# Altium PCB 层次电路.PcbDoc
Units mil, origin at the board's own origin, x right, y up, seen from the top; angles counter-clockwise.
Board outline 3000 x 3000 mil, 4 copper layers (Top Layer, VCC, GND, Bottom Layer), stack 30.634 mil thick; 34 components, 49 nets, 170 pads, 0 vias.
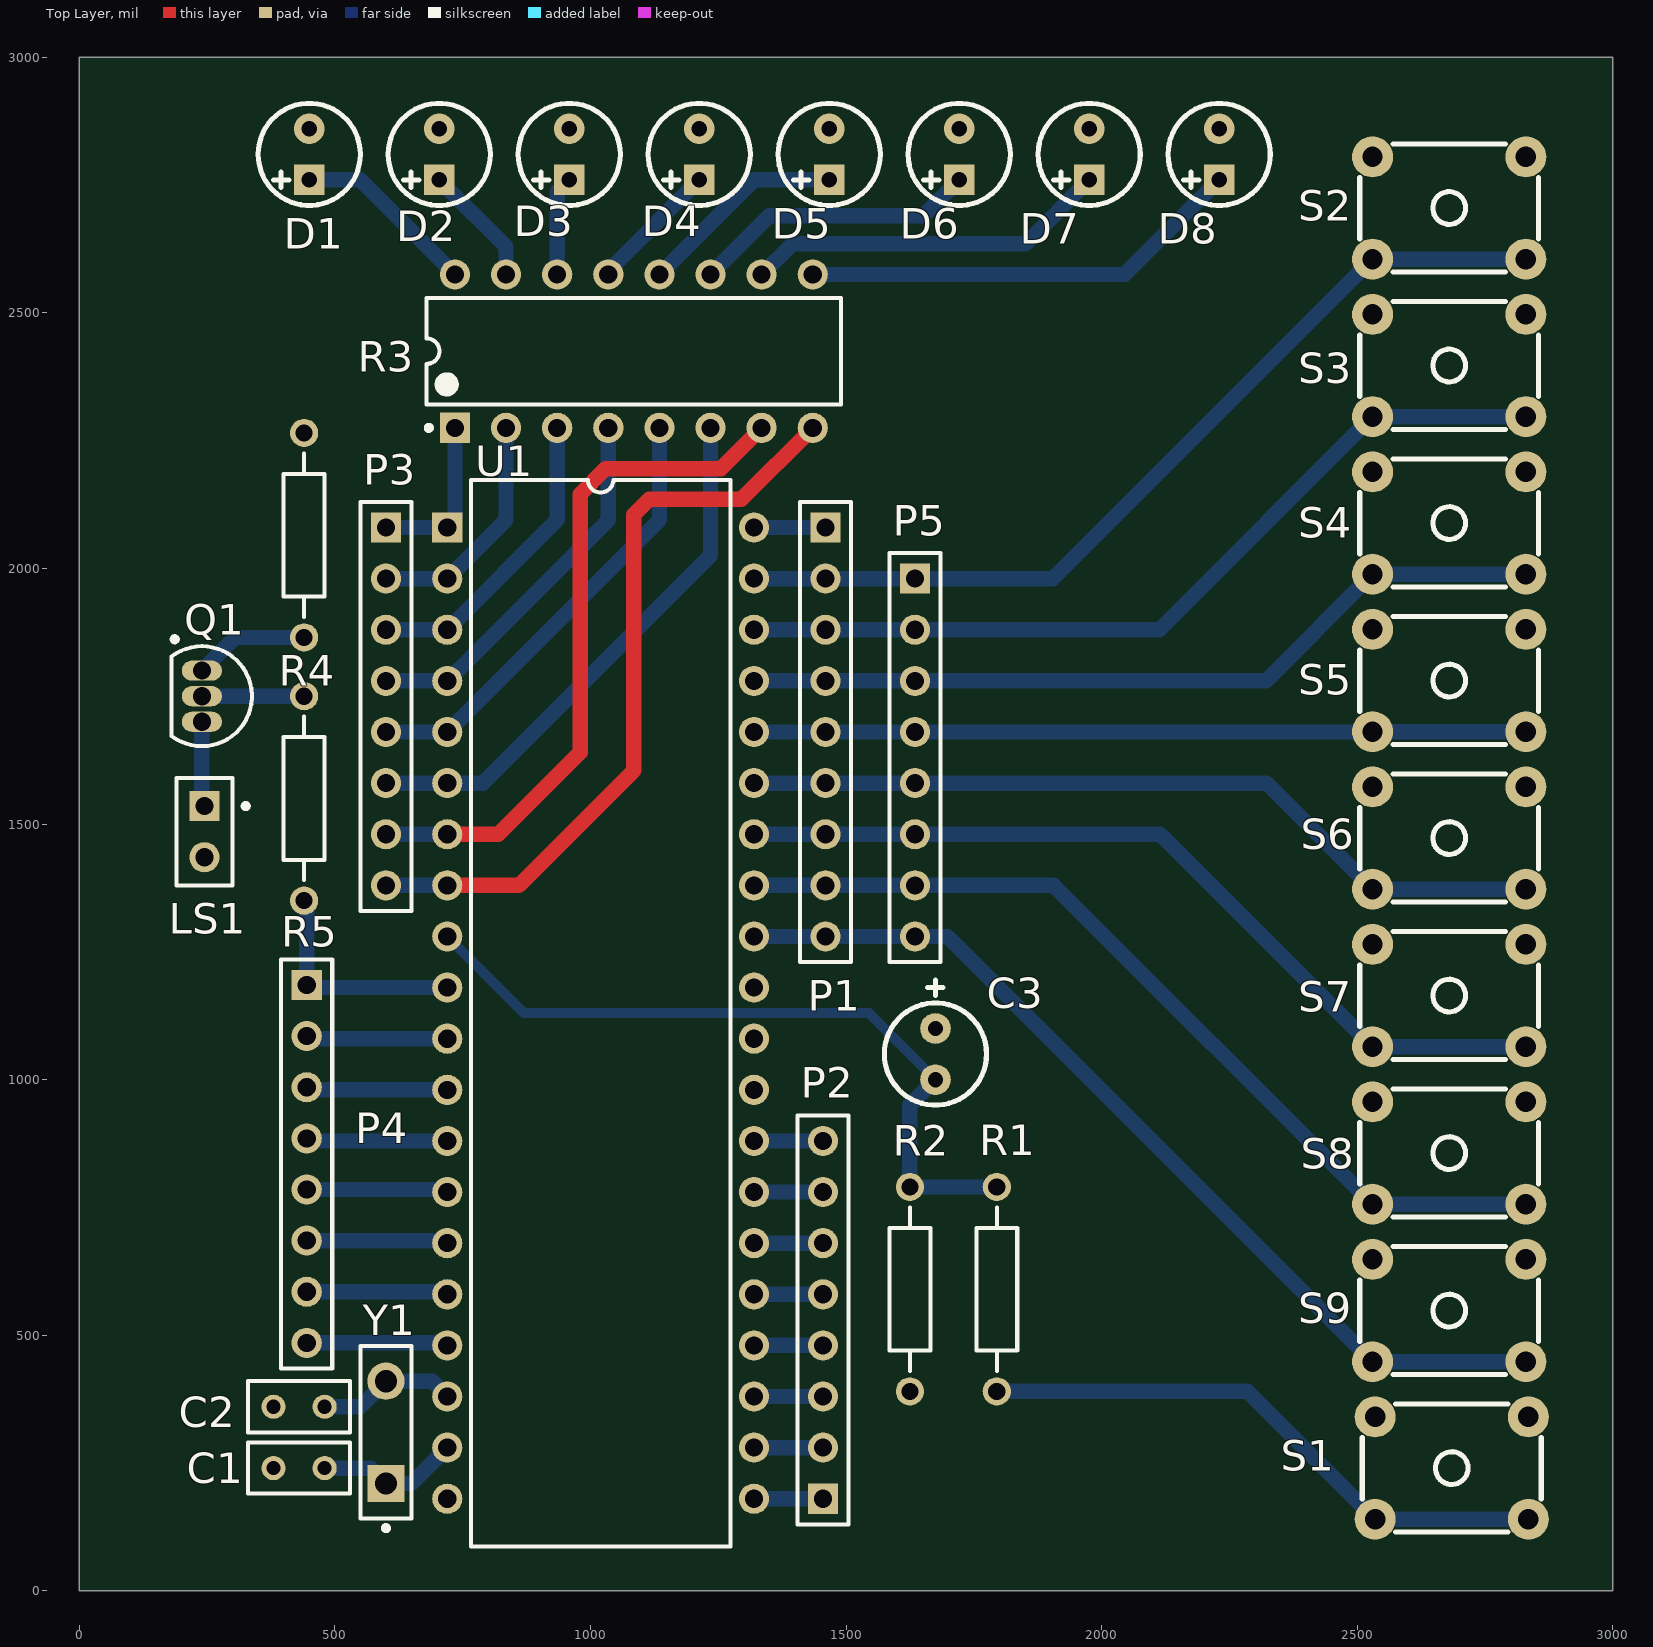
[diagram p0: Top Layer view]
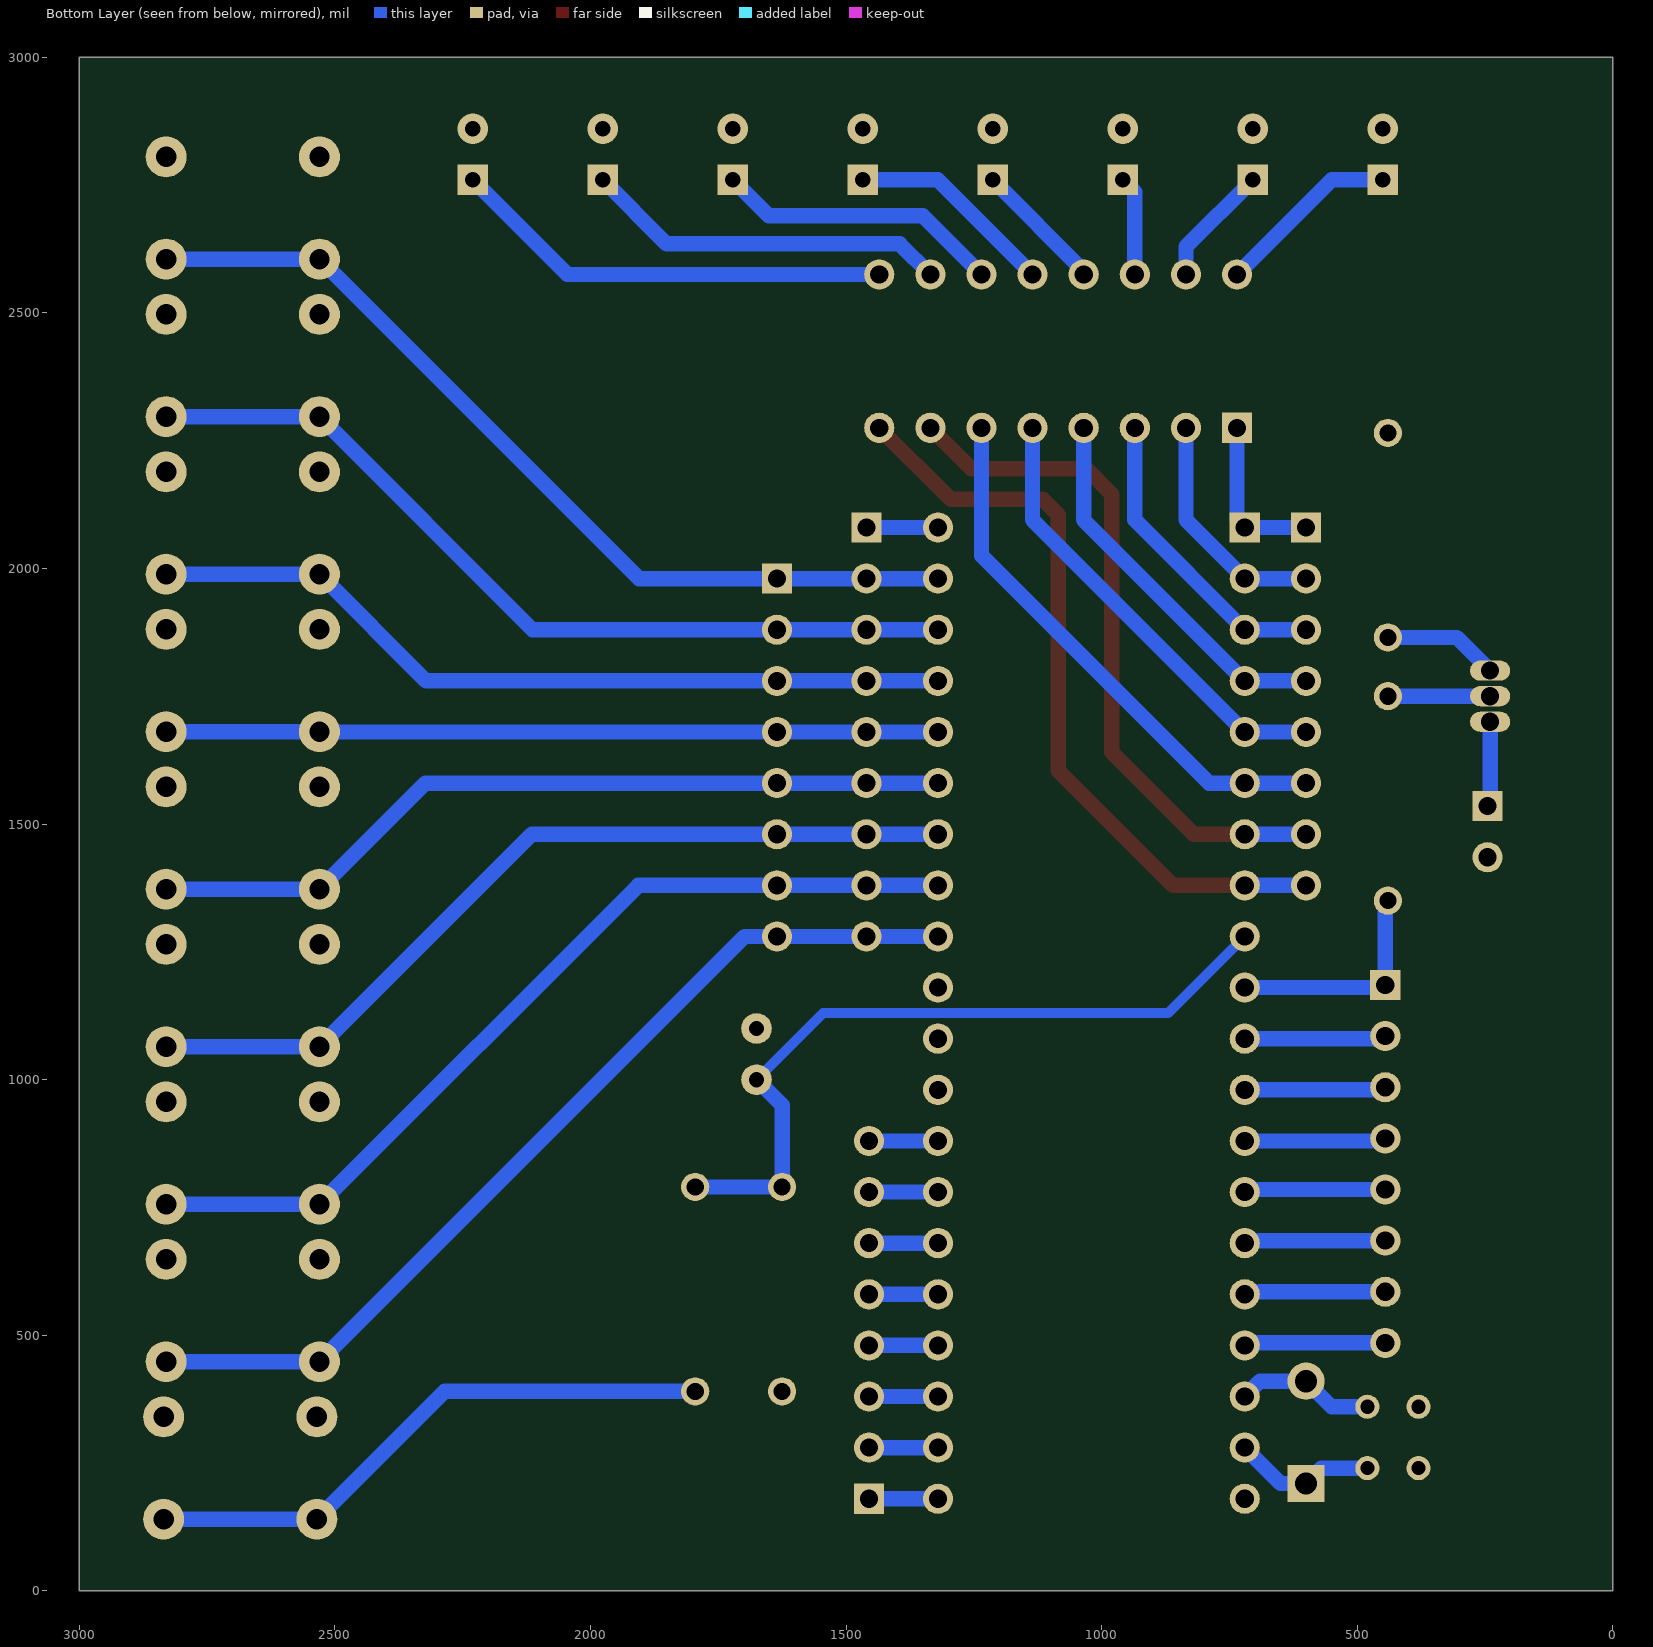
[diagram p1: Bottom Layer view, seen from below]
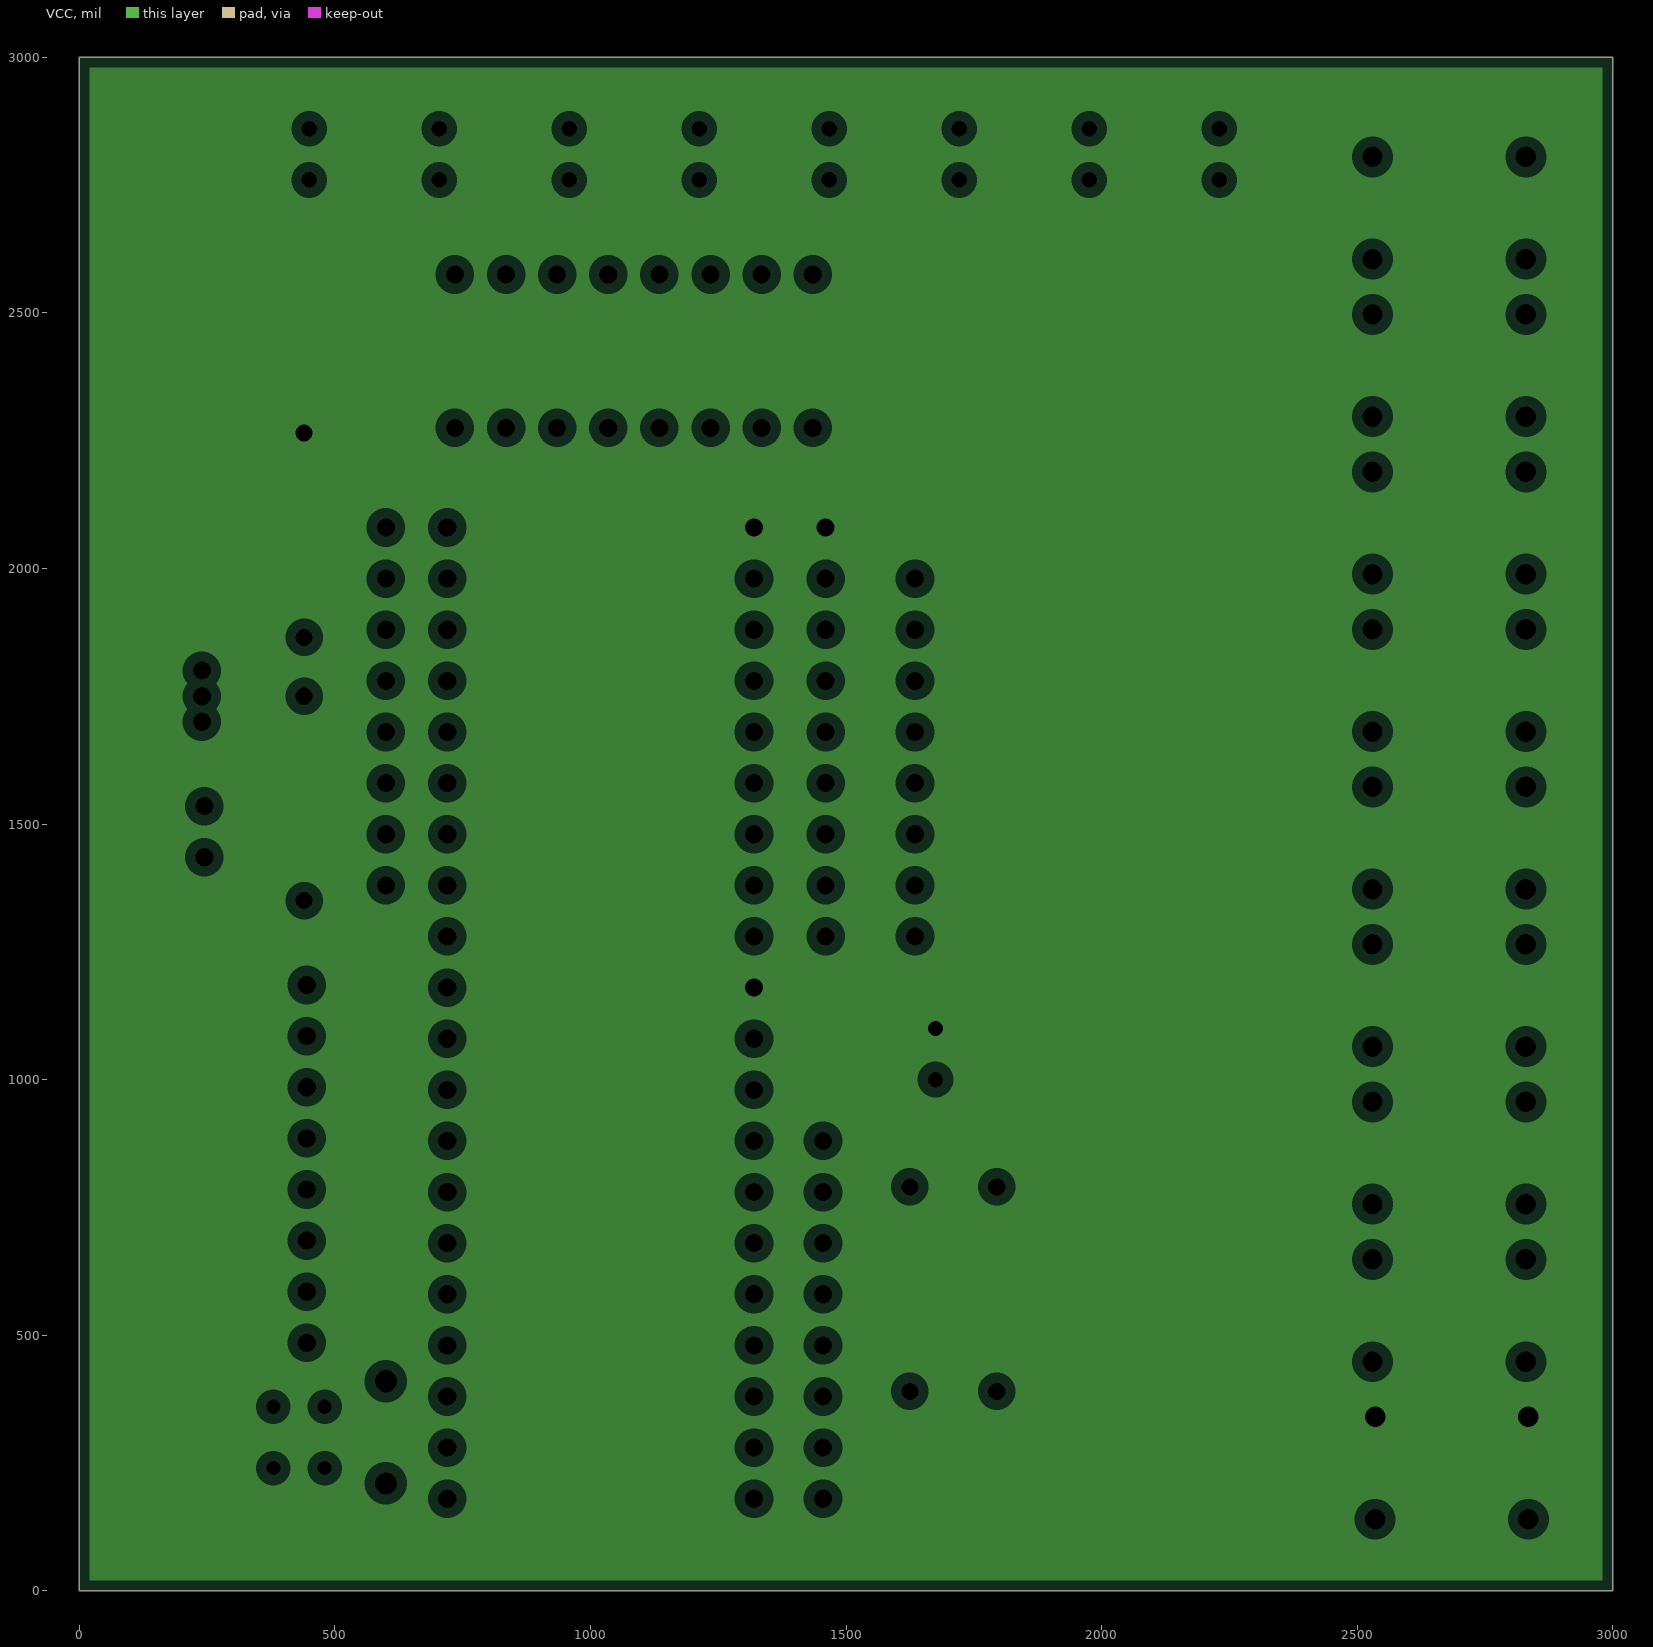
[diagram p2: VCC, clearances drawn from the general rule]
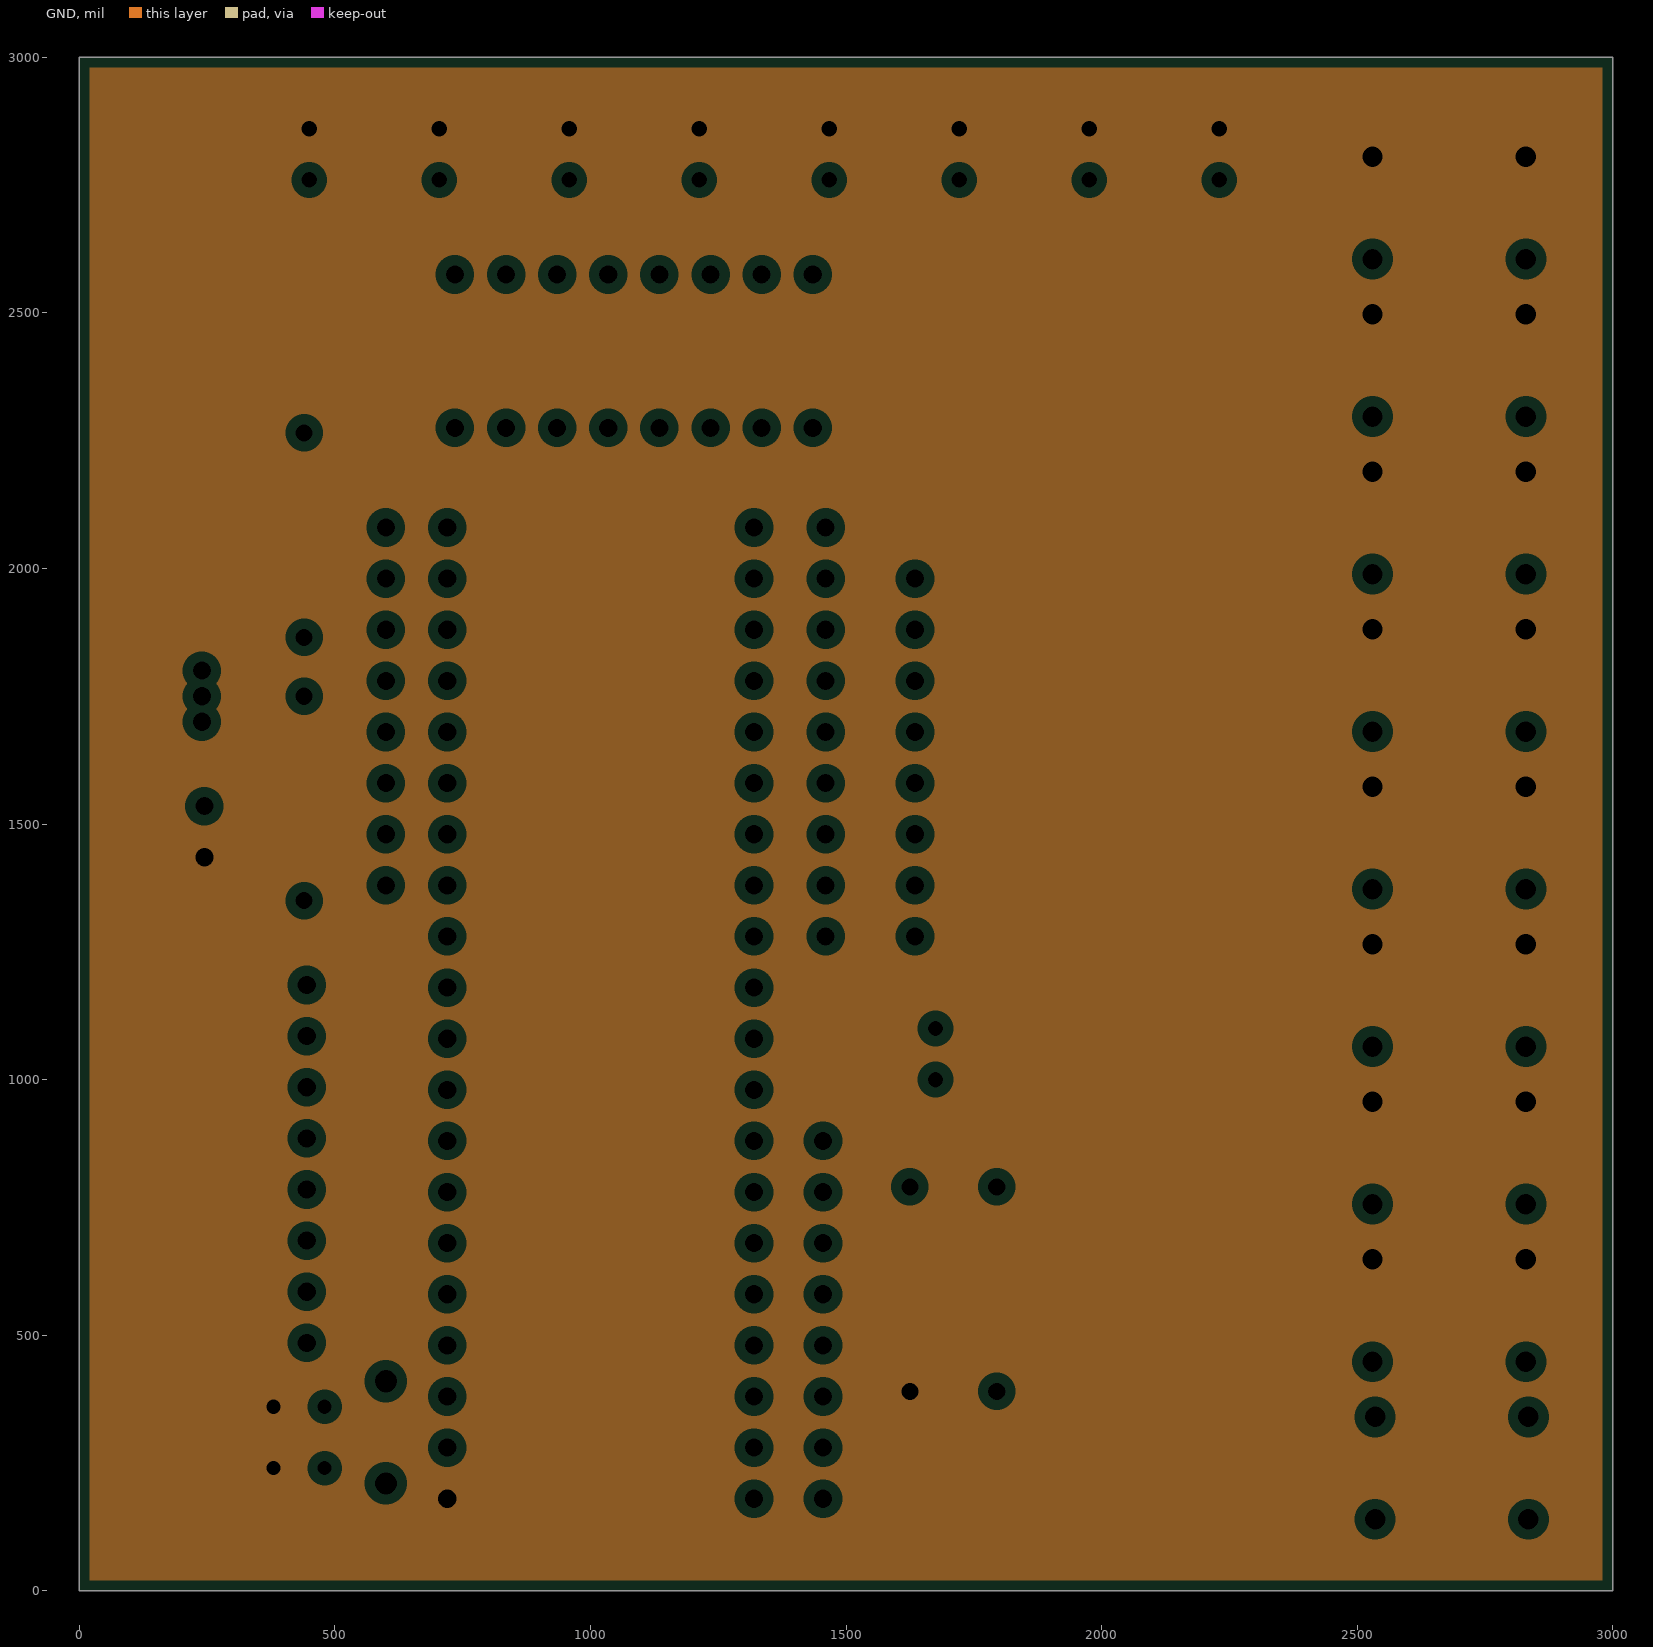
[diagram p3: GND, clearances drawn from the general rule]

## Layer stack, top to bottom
Top Solder: solder mask 0.4, Solder Resist, Dk 3.5
Top Layer: signal copper 1.4
Dielectric 1: core 10, FR-4, Dk 4.2
VCC: plane copper 1.417, net VCC
Dielectric 3: prepreg 5, Dk 4.2
GND: plane copper 1.417, net GND
Dielectric 2: core 10, Dk 4.2
Bottom Layer: signal copper 1.4
Bottom Solder: solder mask 0.4, Solder Resist, Dk 3.5

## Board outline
0,0 0,3000 3000,3000 3000,0

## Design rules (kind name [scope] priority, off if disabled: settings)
Clearance [All] p1: gap=10
PlaneClearance [All] p1: clearance=20
PlaneConnect [All] p1: planeconnectstyle=Relief reliefexpansion=20 reliefentries=4 reliefconductorwidth=10 reliefairgap=10
PolygonConnect [All] p1: connectstyle=Relief reliefconductorwidth=10 reliefentries=4 polygonreliefangle="90 Angle" airgapwidth=10
RoutingVias [All] p1: holewidth=28 width=50 viastyle="Through Hole" minholewidth=28 minwidth=50 maxholewidth=28 maxwidth=50
SolderMaskExpansion [All] p1: expansion=4
Width [All] p1: maxlimit=30 minlimit=10 preferedwidth=30
28 further rules are at their usual default settings.

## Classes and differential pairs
component class U_输出模块: D1 D2 D3 D4 D5 D6 D7 D8 LS1 Q1 R3 R4 R5
component class U_输入模块: S2 S3 S4 S5 S6 S7 S8 S9
component class U_复位、晶振模块: C1 C2 C3 R1 R2 S1 Y1
component class U_CPU模块: P1 P2 P3 P4 P5 U1

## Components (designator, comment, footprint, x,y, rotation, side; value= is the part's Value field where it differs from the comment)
C1 "Cap" RAD-0.1 430,240 r180 top
C2 "Cap" RAD-0.1 430,360 r180 top
C3 "Cap Pol1" 电解电容-100uF 1675,1050 r270 top
D1 "LED0" 发光二极管 450,2810 r90 top
D2 "LED0" 发光二极管 704.29,2810 r90 top
D3 "LED0" 发光二极管 958.57,2810 r90 top
D4 "LED0" 发光二极管 1212.86,2810 r90 top
D5 "LED0" 发光二极管 1467.14,2810 r90 top
D6 "LED0" 发光二极管 1721.43,2810 r90 top
D7 "LED0" 发光二极管 1975.71,2810 r90 top
D8 "LED0" 发光二极管 2230,2810 r90 top
LS1 "Speaker" PIN2 245,1535 r270 top
P1 "1K" HDR1X9 1460,2080 r270 top
P2 "Header 8" HDR1X8 1455,180 r90 top
P3 "Header 8" HDR1X8 600,2080 r270 top
P4 "Header 8" HDR1X8 445,1185 r270 top
P5 "Header 8" HDR1X8 1635,1980 r270 top
Q1 "2N3906" TO-92A 240,1750 r180 top
R1 "Res2" AXIAL-0.4 1795,590 r270 top
R2 "Res2" AXIAL-0.4 1625,590 r90 top
R3 "Res Pack4" DIP-16 1085,2425 r90 top
R4 "Res2" AXIAL-0.4 440,2065 r90 top
R5 "Res2" AXIAL-0.4 440,1550 r90 top
S1 "SW-PB" 轻触开关 2685,240 r180 top
S2 "SW-PB" 轻触开关 2680,2705 r180 top
S3 "SW-PB" 轻触开关 2680,2396.87 r180 top
S4 "SW-PB" 轻触开关 2680,2088.75 r180 top
S5 "SW-PB" 轻触开关 2680,1780.62 r180 top
S6 "SW-PB" 轻触开关 2680,1472.5 r180 top
S7 "SW-PB" 轻触开关 2680,1164.37 r180 top
S8 "SW-PB" 轻触开关 2680,856.25 r180 top
S9 "SW-PB" 轻触开关 2680,548.12 r180 top
U1 "P89C52X2BN" DIP40 1020,1130 r270 top
Y1 "XTAL" SPST-2 600,310 r90 top

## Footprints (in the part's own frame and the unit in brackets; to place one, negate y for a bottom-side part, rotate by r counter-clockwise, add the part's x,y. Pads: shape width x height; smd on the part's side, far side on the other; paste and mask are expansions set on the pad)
AXIAL-0.4 [mm] "Axial Device, Thru-Hole; 2 Leads; 0.4 in Pin Spacing"
  round 1.4 hole 0.85: 1(-5.08,0) 2(5.08,0)
  silkscreen extent -4.06,-1.02 4.06,1.02
DIP40 [mm] "DIP; 40 Leads; Row Spacing 15.24 mm; Pitch 2.54 mm"
  rect 1.5x1.5 hole 0.9: 1(-24.13,-7.62)
  round 1.5 hole 0.9: 2(-21.59,-7.62) 3(-19.05,-7.62) 4(-16.51,-7.62) 5(-13.97,-7.62) 6(-11.43,-7.62) 7(-8.89,-7.62) 8(-6.35,-7.62) 9(-3.81,-7.62) 10(-1.27,-7.62) 11(1.27,-7.62) 12(3.81,-7.62) 13(6.35,-7.62) 14(8.89,-7.62) 15(11.43,-7.62) 16(13.97,-7.62) 17(16.51,-7.62) 18(19.05,-7.62) 19(21.59,-7.62) 20(24.13,-7.62) 21(24.13,7.62) 22(21.59,7.62) 23(19.05,7.62) 24(16.51,7.62) 25(13.97,7.62) 26(11.43,7.62) 27(8.89,7.62) 28(6.35,7.62) 29(3.81,7.62) 30(1.27,7.62) 31(-1.27,7.62) 32(-3.81,7.62) 33(-6.35,7.62) 34(-8.89,7.62) 35(-11.43,7.62) 36(-13.97,7.62) 37(-16.51,7.62) 38(-19.05,7.62) 39(-21.59,7.62) 40(-24.13,7.62)
  silkscreen extent -26.5,-6.45 26.5,6.45
DIP-16 [mm] "DIP; 16 Leads; Row Spacing 7.62 mm; Pitch 2.54 mm"
  rect 1.5x1.5 hole 0.9: 1(-3.81,8.89)
  round 1.5 hole 0.9: 2(-3.81,6.35) 3(-3.81,3.81) 4(-3.81,1.27) 5(-3.81,-1.27) 6(-3.81,-3.81) 7(-3.81,-6.35) 8(-3.81,-8.89) 9(3.81,-8.89) 10(3.81,-6.35) 11(3.81,-3.81) 12(3.81,-1.27) 13(3.81,1.27) 14(3.81,3.81) 15(3.81,6.35) 16(3.81,8.89)
  silkscreen extent -3.93,-10.3 2.65,10.31, body extent -3.6,-10.28 3.6,10.28, height 5.08
HDR1X8 [mm] "Connector; Header; 8 Position"
  rect 1.5x1.5 hole 0.9: 1(0,0)
  round 1.5 hole 0.9: 2(2.54,0) 3(5.08,0) 4(7.62,0) 5(10.16,0) 6(12.7,0) 7(15.24,0) 8(17.78,0)
  silkscreen extent -1.27,-1.27 19.05,1.27
HDR1X9 [mm] "Connector; Header; 9 Position"
  rect 1.5x1.5 hole 0.9: 1(0,0)
  round 1.5 hole 0.9: 2(2.54,0) 3(5.08,0) 4(7.62,0) 5(10.16,0) 6(12.7,0) 7(15.24,0) 8(17.78,0) 9(20.32,0)
  silkscreen extent -1.27,-1.27 21.59,1.27
PIN2 [mm] "Photosensitive Diode; 2 Leads"
  rect 1.5x1.5 hole 0.9: 1(0,0)
  round 1.5 hole 0.9: 2(2.54,0)
  silkscreen extent -1.4,-1.4 3.94,2.18
RAD-0.1 [mm] "Radial Cap, Thru-Hole; 2 Leads; 0.1 in Pin Spacing"
  round 1.2 hole 0.7: 1(-1.27,0) 2(1.27,0)
  silkscreen extent -2.54,-1.27 2.54,1.27
SPST-2 [mm] "Switch; 2 Leads"
  rect 1.85x1.85 hole 1.1: 1(-2.54,0)
  round 1.85 hole 1.1: 2(2.54,0)
  silkscreen extent -4.89,-1.27 4.28,1.27
TO-92A [mm] "TO, Flat Index; 3 In-Line, Axial Leads; Body Dia. 4.5mm; Leads 0.51 x 0.48 mm (max)"
  oval 2x1 hole 0.9: 1(0,-1.27) 2(0,0) 3(0,1.27)
  silkscreen extent -2.48,-2.95 1.5,2.48, body extent -2.48,-2.5 1.5,2.5, height 6.86
发光二极管 [mil]
  rect 60x60 hole 30: 1(-50,0)
  round 60 hole 30: 2(50,0)
  silkscreen extent -100,-100 100,100
电解电容-100uF [mil]
  round 60 hole 30: 1(-50,0) 2(50,0)
  silkscreen extent -145,-100 100,100
轻触开关 [mil]
  round 80 hole 40: 1(-150,100) 1(150,100) 2(-150,-100) 2(150,-100)
  silkscreen extent -175,-125 175,125

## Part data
C1 C2: "Capacitor"
C3: "Polarized Capacitor (Radial)"
D1 D2 D3 D4 D5 D6 D7 D8: "Typical INFRARED GaAs LED"
LS1: "Loudspeaker"
P1: library part MHDR1X9, "Header, 9-Pin"
P2 P3 P4 P5: "Header, 8-Pin"
Q1: "PNP General Purpose Amplifier"
R1 R2 R4 R5: "Resistor"
R3: "Isolated Resistor Network"
S1 S2 S3 S4 S5 S6 S7 S8 S9: "Switch"
U1: "80C51 8-Bit Flash Microcontroller Family, 8 kB Flash"
Y1: "Crystal Oscillator"

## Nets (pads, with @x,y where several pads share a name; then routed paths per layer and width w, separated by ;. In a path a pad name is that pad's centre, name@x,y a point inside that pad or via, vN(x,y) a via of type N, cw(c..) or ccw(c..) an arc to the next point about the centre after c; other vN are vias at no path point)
A: D1.1 R3.16 | length 361.6
  Bottom Layer w30: D1.1 550,2760 R3.16
A0: P1.2 P5.1 S2.1 U1.39 | length 1768.9
  Bottom Layer w30: U1.39 P1.2 P5.1 1905,1980 2530,2605 S2.1@2830,2605
A1: P1.3 P5.2 S3.1 U1.38 | length 1682.7
  Bottom Layer w30: U1.38 P1.3 P5.2 2113.13,1880 2530,2296.87 S3.1@2830,2296.87
A2: P1.4 P5.3 S4.1 U1.37 | length 1596.5
  Bottom Layer w30: U1.37 P1.4 P5.3 2321.25,1780 2530,1988.75 S4.1@2830,1988.75
A3: P1.5 P5.4 S5.1 U1.36 | length 1510.3
  Bottom Layer w30: U1.36 P1.5 P5.4 2529.38,1680 2530,1680.62 S5.1@2830,1680.62
A4: P1.6 P5.5 S6.1 U1.35 | length 1595.9
  Bottom Layer w30: U1.35 P1.6 P5.5 2322.5,1580 2530,1372.5 S6.1@2830,1372.5
A5: P1.7 P5.6 S7.1 U1.34 | length 1682.2
  Bottom Layer w30: U1.34 P1.7 P5.6 2114.37,1480 2530,1064.37 S7.1@2830,1064.37
A6: P1.8 P5.7 S8.1 U1.33 | length 1768.4
  Bottom Layer w30: U1.33 P1.8 P5.7 1906.25,1380 2530,756.25 S8.1@2830,756.25
A7: P1.9 P5.8 S9.1 U1.32 | length 1854.6
  Bottom Layer w30: U1.32 P1.9 P5.8 1698.12,1280 2530,448.12 S9.1@2830,448.12
B: D2.1 R3.15 | length 239.1
  Bottom Layer w30: D2.1 835,2629.29 R3.15
C: D3.1 R3.14 | length 194.8
  Bottom Layer w30: R3.14 935,2736.43 D3.1
D: D4.1 R3.13 | length 258.7
  Bottom Layer w30: R3.13 1035,2582.14 D4.1
D0: P3.1 R3.1 U1.1 | length 321.2
  Bottom Layer w30: P3.1 U1.1 735,2095 R3.1
D1: P3.2 R3.2 U1.2 | length 462.6
  Bottom Layer w30: P3.2 U1.2 835,2095 R3.2
D2: P3.3 R3.3 U1.3 | length 604.1
  Bottom Layer w30: P3.3 U1.3 935,2095 R3.3
D3: P3.4 R3.4 U1.4 | length 745.5
  Bottom Layer w30: P3.4 U1.4 1035,2095 R3.4
D4: P3.5 R3.5 U1.5 | length 886.9
  Bottom Layer w30: P3.5 U1.5 1135,2095 R3.5
D5: P3.6 R3.6 U1.6 | length 1069.3
  Bottom Layer w30: P3.6 U1.6 790,1580 1235,2025 R3.6
D6: P3.7 R3.7 U1.7 | length 1360.1
  Top Layer w30: U1.7 820,1480 980,1640 980,2145 1030,2195 1255,2195 R3.7
  Bottom Layer w30: P3.7 U1.7
D7: P3.8 R3.8 U1.8 | length 1498.6
  Top Layer w30: U1.8 860,1380 1085,1605 1085,2105 1115,2135 1295,2135 R3.8
  Bottom Layer w30: P3.8 U1.8
D8: P2.1 U1.21 | length 135
  Bottom Layer w30: U1.21 P2.1
D9: P2.2 U1.22 | length 135
  Bottom Layer w30: U1.22 P2.2
D10: P2.3 U1.23 | length 135
  Bottom Layer w30: U1.23 P2.3
D11: P2.4 U1.24 | length 135
  Bottom Layer w30: U1.24 P2.4
D12: P2.5 U1.25 | length 135
  Bottom Layer w30: U1.25 P2.5
D13: P2.6 U1.26 | length 135
  Bottom Layer w30: U1.26 P2.6
D14: P2.7 U1.27 | length 135
  Bottom Layer w30: U1.27 P2.7
D15: P2.8 U1.28 | length 135
  Bottom Layer w30: U1.28 P2.8
E: D5.1 R3.12 | length 408.8
  Bottom Layer w30: R3.12 1320,2760 D5.1
F: D6.1 R3.11 | length 563.1
  Bottom Layer w30: R3.11 1350,2690 1651.43,2690 D6.1
G: D7.1 R3.10 | length 717.3
  Bottom Layer w30: R3.10 1395,2635 1850.71,2635 D7.1
GND: C1.2 C2.2 D1.2 D2.2 D3.2 D4.2 D5.2 D6.2 D7.2 D8.2 LS1.2 R2.1 S2.2 S3.2 S4.2 S5.2 S6.2 S7.2 S8.2 S9.2 U1.20
H: D8.1 R3.9 | length 871.6
  Bottom Layer w30: R3.9 2045,2575 D8.1
NetC1_1: C1.1 U1.19 Y1.1 | length 281.4
  Bottom Layer w30: C1.1 570,240 Y1.1 650,210 U1.19
NetC2_1: C2.1 U1.18 Y1.2 | length 273.1
  Bottom Layer w30: C2.1 550,360 Y1.2 690,410 U1.18
NetC3_2: C3.2 R1.1 R2.2 U1.9 | length 1471.7
  Bottom Layer w20: U1.9 870,1130 1545,1130 C3.2
  Bottom Layer w30: C3.2 1625,950 R2.2 R1.1
NetLS1_1: LS1.1 Q1.3 | length 167.1
  Bottom Layer w30: Q1.3 240,1540 LS1.1
NetQ1_1: Q1.1 R4.1 | length 226.9
  Bottom Layer w30: Q1.1 305,1865 R4.1
NetQ1_2: Q1.2 R5.2 | length 200
  Bottom Layer w30: Q1.2 R5.2
NetR1_2: R1.2 S1.1 | length 1143.6
  Bottom Layer w30: R1.2 2285,390 2535,140 S1.1@2835,140
P30: P4.1 R5.1 U1.10 | length 451.2
  Bottom Layer w30: R5.1 445,1345 P4.1 450,1180 U1.10 U1.10@715,1185
P31: P4.2 U1.11 | length 277.1
  Bottom Layer w30: P4.2 450,1080 U1.11
P32: P4.3 U1.12 | length 277.1
  Bottom Layer w30: P4.3 450,980 U1.12
P33: P4.4 U1.13 | length 277.1
  Bottom Layer w30: P4.4 450,880 U1.13
P34: P4.5 U1.14 | length 277.1
  Bottom Layer w30: P4.5 715,785 U1.14
P35: P4.6 U1.15 | length 277.1
  Bottom Layer w30: P4.6 715,685 U1.15
P36: P4.7 U1.16 | length 277.1
  Bottom Layer w30: P4.7 715,585 U1.16
P37: P4.8 U1.17 | length 277.1
  Bottom Layer w30: P4.8 715,485 U1.17
VCC: C3.1 P1.1 R4.2 S1.2 U1.31 U1.40 | length 140
  Bottom Layer w30: U1.40 P1.1
pads on no net: U1.29 U1.30

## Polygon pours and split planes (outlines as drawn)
VCC on VCC (split plane): 2979.9,20.1 20.1,20.1 20.1,2979.9 2979.9,2979.9
GND on GND (split plane): 2979.9,20.1 20.1,20.1 20.1,2979.9 2979.9,2979.9

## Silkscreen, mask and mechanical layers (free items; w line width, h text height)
Mechanical 1:
  lines w10: 0,0 3000,0 3000,3000 0,3000 0,0 ; 50,50 2950,50 2950,2950 50,2950 50,50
